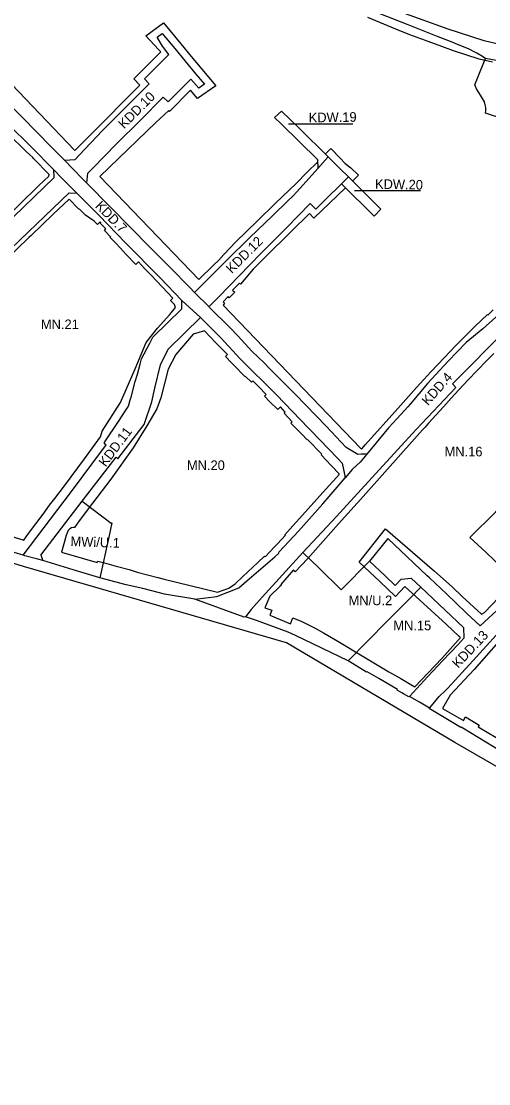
# Model space of a CAD drawing. Extents: x 7418991 to 7423142, y 5547704 to 5549547.
# Drawn here: x 7419792 to 7420035, y 5547967 to 5548519 of the extents above; entities that cross this region are included whole.
import ezdxf

# ---------------------------------------------------------------- set-up
doc = ezdxf.new("R2010")
doc.units = 0
for name, color, linetype in [('LIN_Linia Zabudowy Nieprzekraczalna', 7, 'Continuous'), ('LIN_linie_rozgraniczajace', 7, 'Continuous'), ('TXT_Oznaczenia_przeznaczen', 7, 'Continuous')]:
    doc.layers.add(name, color=color, linetype=linetype)

msp = doc.modelspace()

# ---------------------------------------------------------------- linework, layer by layer
at = {"layer": 'LIN_Linia Zabudowy Nieprzekraczalna'}
for p, q in [((7419717.86, 5548558.33), (7419819.96, 5548451.81)), ((7419832.95, 5548438.26), (7419884.28, 5548384.7)), ((7419821.98, 5548421.3), (7419816.95, 5548426.47))]:
    msp.add_line(p, q, dxfattribs=at)
for points in [[(7419856.71, 5548511.25), (7419866, 5548518.06), (7419874.96, 5548507.22)], [(7420036.89, 5548497.59), (7420029.91, 5548499.2), (7420016.68, 5548503.49), (7420010.54, 5548505.74), (7420001.59, 5548509.01), (7420000.65, 5548509.37), (7419999.62, 5548509.77), (7419994.01, 5548511.91), (7419986.71, 5548514.81), (7419972.13, 5548520.75)], [(7419864.51, 5548502.97), (7419863.34, 5548504.23), (7419856.71, 5548511.25)], [(7419874.96, 5548507.22), (7419880.38, 5548500.66), (7419885.89, 5548494.04)], [(7419853.63, 5548485.71), (7419850.46, 5548488.93), (7419864.51, 5548502.97)], [(7419885.89, 5548494.04), (7419893.15, 5548485.32), (7419883.63, 5548478.82), (7419880.01, 5548483)], [(7419819.96, 5548451.81), (7419824.06, 5548455.92), (7419835.48, 5548467.29), (7419845.95, 5548477.88), (7419853.63, 5548485.71)], [(7419880.01, 5548483), (7419869.06, 5548472.02), (7419868.65, 5548472.46)], [(7419868.65, 5548472.46), (7419862.06, 5548466.29), (7419832.95, 5548438.26)], [(7419781.33, 5548414.06), (7419801.15, 5548433.63), (7419806.37, 5548438.5), (7419806.42, 5548438.57), (7419806.59, 5548439.19), (7419806.59, 5548439.29), (7419798.4, 5548447.67), (7419798.01, 5548448.09), (7419794.66, 5548451.16), (7419785.41, 5548460.15)], [(7419950.06, 5548449.94), (7419952.85, 5548452.74), (7419957.74, 5548447.74), (7419960.34, 5548445.06), (7419963.22, 5548442.68), (7419967.33, 5548438.94), (7419964.17, 5548435.9)], [(7419927.77, 5548427.86), (7419934.85, 5548434.69), (7419940.39, 5548440.24), (7419946.07, 5548445.94)], [(7419960.56, 5548432.43), (7419944.13, 5548416.63), (7419941.75, 5548418.99), (7419932.21, 5548409.42), (7419918.92, 5548396.51), (7419912.58, 5548390.1), (7419906.02, 5548382.26), (7419905.49, 5548382.8), (7419901.88, 5548379.27), (7419903.02, 5548378.13), (7419900.1, 5548375.3), (7419899.58, 5548375.86), (7419896.89, 5548373.22), (7419897.74, 5548372.37), (7419896.98, 5548371.46), (7419968.26, 5548297.09), (7419968.51, 5548296.89), (7419968.91, 5548296.71), (7419968.99, 5548296.78), (7419970.97, 5548299.07), (7419987.7, 5548317.75), (7419989.04, 5548319.29), (7419997.5, 5548328.57), (7420005.13, 5548337), (7420011.92, 5548344.19), (7420017.73, 5548350.26), (7420022.47, 5548355.16), (7420027.89, 5548360.43), (7420034.37, 5548366.6), (7420034.6, 5548366.36), (7420037.35, 5548369.05)], [(7419816.95, 5548426.47), (7419808.61, 5548418.6), (7419797.18, 5548407.61), (7419796, 5548406.59), (7419783.69, 5548394.56), (7419776.16, 5548386.69), (7419769.62, 5548379.68), (7419753.04, 5548361.82), (7419741.07, 5548348.15), (7419710.14, 5548308.14)], [(7419884.28, 5548384.7), (7419892.01, 5548392.15), (7419894.73, 5548394.79), (7419894.67, 5548394.85), (7419897.35, 5548397.78), (7419903.59, 5548404.31), (7419914.74, 5548415.22), (7419924, 5548424.21), (7419927.77, 5548427.86)], [(7419825.49, 5548418.18), (7419822.22, 5548421.53), (7419821.98, 5548421.3)], [(7419831.61, 5548413.28), (7419829.86, 5548415.05), (7419825.49, 5548418.18)], [(7419838.26, 5548406.49), (7419838.55, 5548406.78), (7419835.26, 5548410.28), (7419835.93, 5548411.01), (7419833.08, 5548413.96), (7419833.37, 5548414.29), (7419833.04, 5548414.62), (7419831.61, 5548413.28)], [(7419851.5, 5548392.62), (7419846.6, 5548397.74), (7419843.51, 5548401.11), (7419841.11, 5548403.63), (7419838.26, 5548406.49)], [(7419869.61, 5548373.9), (7419870.87, 5548375.11), (7419862.42, 5548383.88), (7419862.16, 5548384.19), (7419859.91, 5548386.58), (7419857.53, 5548389.07), (7419856.17, 5548390.51), (7419852.89, 5548393.95), (7419851.5, 5548392.62)], [(7419872.18, 5548370.2), (7419871.63, 5548371.71), (7419869.61, 5548373.9)], [(7419793.36, 5548249.33), (7419795.77, 5548252.78), (7419803.35, 5548262.84), (7419806.75, 5548267.48), (7419809.48, 5548270.98), (7419814.44, 5548277.62), (7419824.91, 5548291.64), (7419833.15, 5548303.02), (7419834.02, 5548306.04), (7419843.53, 5548320.88), (7419851.31, 5548338.35), (7419857.02, 5548351.96), (7419862.92, 5548359.42), (7419869.17, 5548366.65), (7419872.18, 5548370.2)], [(7419881.32, 5548356.39), (7419872.45, 5548345.73), (7419868.34, 5548338.17), (7419864.5, 5548323.35), (7419862.57, 5548317.52), (7419857.38, 5548308.79), (7419850.18, 5548297.29), (7419838.64, 5548281.01), (7419829.13, 5548268.5), (7419822.19, 5548259.32), (7419819.63, 5548255.97), (7419819.17, 5548255.99), (7419818.13, 5548255.74), (7419817.23, 5548255.23), (7419816.38, 5548254.35), (7419815.83, 5548253.18), (7419815.45, 5548251.72), (7419812.99, 5548243.17)], [(7419898.13, 5548344.68), (7419899.18, 5548345.71), (7419893.22, 5548351.88), (7419887.23, 5548358.09), (7419881.32, 5548356.39)], [(7420037.56, 5548346.25), (7420034.04, 5548342.63), (7420028.9, 5548337.41), (7420024.36, 5548332.64), (7420019.35, 5548327.46), (7420015.38, 5548323.04), (7420011.45, 5548318.67), (7420003.62, 5548310.07), (7420001.92, 5548308.08), (7420000.59, 5548306.72), (7419983.76, 5548287.82), (7419966.88, 5548268.93), (7419966.59, 5548268.61), (7419956.98, 5548257.85), (7419940.9, 5548239.89), (7419937.52, 5548236.23), (7419934.39, 5548232.95), (7419933.38, 5548233.85), (7419926.89, 5548226.36), (7419927.23, 5548226.06), (7419926.49, 5548225.35), (7419921.2, 5548220.29), (7419918.67, 5548214.26), (7419922.2, 5548213.02), (7419921.13, 5548210.47), (7419931.88, 5548205.92), (7419933.15, 5548209.01), (7419937.77, 5548207.07), (7419944.69, 5548203.64), (7419949.06, 5548201.24), (7419957.46, 5548196.33), (7419968.37, 5548189.8), (7419975.29, 5548185.57), (7419983.04, 5548180.97), (7419989.2, 5548177.44), (7419994.53, 5548174.32), (7419996.6, 5548173.1), (7420010.57, 5548187.86), (7420019.11, 5548197.39), (7420020.09, 5548198.53), (7420020.04, 5548198.89), (7420019.63, 5548199.37), (7420012.79, 5548205.73), (7419991.3, 5548225.28), (7419986.55, 5548220.09), (7419978.32, 5548227.86), (7419967.58, 5548238), (7419981.37, 5548255.15), (7420006.78, 5548233.26), (7420015.93, 5548225.04), (7420021.1, 5548220.1), (7420031.14, 5548210.94), (7420032.76, 5548211.73), (7420051.25, 5548231.24)], [(7419908.23, 5548334.34), (7419902.47, 5548340.23), (7419901.22, 5548341.53), (7419898.13, 5548344.68)], [(7419918.39, 5548324.14), (7419919.32, 5548325.06), (7419915.43, 5548329.03), (7419914.39, 5548330.11), (7419912.45, 5548332.17), (7419911.64, 5548331.37), (7419908.46, 5548334.57), (7419908.23, 5548334.34)], [(7419925.31, 5548317.17), (7419921.12, 5548321.39), (7419918.39, 5548324.14)], [(7419932.21, 5548310.17), (7419932.89, 5548310.84), (7419928.62, 5548315.28), (7419929.25, 5548315.92), (7419926.7, 5548318.53), (7419926.09, 5548317.93), (7419925.31, 5548317.17)], [(7419940.57, 5548301.4), (7419937.78, 5548304.36), (7419932.21, 5548310.17)], [(7419947.82, 5548293.7), (7419948.18, 5548294.05), (7419940.78, 5548301.6), (7419940.57, 5548301.4)], [(7419953.08, 5548288.18), (7419950.5, 5548290.94), (7419948.01, 5548293.49), (7419947.82, 5548293.7)], [(7419954.23, 5548280.24), (7419957.18, 5548283.43), (7419957.3, 5548283.76), (7419957.27, 5548283.84), (7419956.92, 5548284.22), (7419953.83, 5548287.45), (7419953.08, 5548288.18)], [(7419929.05, 5548252.18), (7419933.2, 5548256.79), (7419936.62, 5548260.59), (7419945.7, 5548270.69), (7419953.79, 5548279.72), (7419954.23, 5548280.24)], [(7419721.51, 5548271.48), (7419724.57, 5548270.33), (7419733.19, 5548267.59), (7419747.21, 5548263.26), (7419762.91, 5548258.58), (7419769.84, 5548256.52), (7419780.42, 5548253.35), (7419793.36, 5548249.33)], [(7419918.37, 5548241.07), (7419918.8, 5548240.66), (7419923.72, 5548245.92), (7419925.18, 5548247.48), (7419929.34, 5548251.91), (7419929.05, 5548252.18)], [(7419812.99, 5548243.17), (7419831.57, 5548237.75), (7419831.77, 5548238.47), (7419835.32, 5548237.55), (7419841.41, 5548235.91), (7419848.1, 5548234.06), (7419852.27, 5548232.73), (7419863.05, 5548230), (7419866.32, 5548229.05), (7419894, 5548222.39)], [(7419894, 5548222.39), (7419899.88, 5548224.42), (7419903.28, 5548226.66), (7419907.12, 5548230.44), (7419914.92, 5548237.75), (7419918.37, 5548241.07)], [(7420046.24, 5548203.58), (7420027.46, 5548182.2), (7420014.87, 5548168.91), (7420010.87, 5548161.92), (7420021.77, 5548155.69), (7420022.83, 5548157.56), (7420030.02, 5548153.25), (7420029.5, 5548152.36), (7420038.8, 5548146.89)]]:
    msp.add_lwpolyline(points, dxfattribs=at)
at = {"layer": 'LIN_linie_rozgraniczajace'}
for p, q in [((7420042.19, 5548506.4), (7420032.55, 5548508.76)), ((7419826.12, 5548434.85), (7419826.66, 5548439.89)), ((7419882.1, 5548378.06), (7419898.9, 5548394.76)), ((7419894.69, 5548375.81), (7419889.72, 5548370.73)), ((7419941.38, 5548307.6), (7419924.62, 5548324.86)), ((7419982.47, 5548250.14), (7419973.01, 5548238.37)), ((7419802.26, 5548241.61), (7419803.19, 5548238.7))]:
    msp.add_line(p, q, dxfattribs=at)
for points in [[(7420032.55, 5548508.76), (7420013.86, 5548514.78), (7419989.73, 5548523.36), (7419965.32, 5548534.48), (7419945.27, 5548544.1)], [(7420325.12, 5547967), (7420017.42, 5548144.29), (7419955.38, 5548181), (7419929.91, 5548196.08), (7419793.21, 5548235.75), (7419596.81, 5548296.15), (7419558.42, 5548312.8), (7419546.12, 5548320.07), (7419546.12, 5548320.06), (7419504.75, 5548344.51), (7419463.08, 5548377.86), (7419457.25, 5548382.53), (7419446.13, 5548391.44), (7419408.3, 5548414.15), (7419403.6, 5548416.97), (7419403.3, 5548427.68), (7419403.28, 5548428.22), (7419403.44, 5548430.77), (7419403.61, 5548432.44), (7419404.03, 5548435.15), (7419413.56, 5548470.15), (7419425.07, 5548507.35), (7419431.26, 5548527.19)], [(7420028.02, 5548502.66), (7420024.52, 5548504.56), (7420017.85, 5548507.22), (7420016.8, 5548507.66), (7420007.79, 5548511.19), (7419993.01, 5548516.98), (7419973.97, 5548524.43)], [(7419730.82, 5548520.64), (7419749.71, 5548501.07), (7419751.69, 5548499.35), (7419754.06, 5548496.96), (7419759.39, 5548491.54), (7419762.83, 5548488.04), (7419767.29, 5548483.57), (7419775.92, 5548474.95), (7419785.15, 5548465.67), (7419797.38, 5548453.56), (7419809.02, 5548441.68), (7419813.1, 5548437.36), (7419820.94, 5548429.57), (7419832.45, 5548417.92), (7419846.22, 5548403.72), (7419864.18, 5548385.61), (7419875.46, 5548373.86), (7419885.22, 5548364.96), (7419895.76, 5548354.52), (7419905.88, 5548343.51), (7419924.62, 5548324.86)], [(7419868.8, 5548501.6), (7419865.39, 5548505.89), (7419862.59, 5548510.6), (7419865.32, 5548512.6), (7419871.87, 5548504.67)], [(7419868.8, 5548501.6), (7419856.1, 5548488.91), (7419858.55, 5548486.43), (7419846.59, 5548474.4), (7419834.23, 5548462.17), (7419822.13, 5548449.38)], [(7419871.87, 5548504.67), (7419877.3, 5548498.11), (7419882.82, 5548491.48)], [(7420102.05, 5548487.44), (7420098.3, 5548487.29), (7420094.85, 5548487.14), (7420080.12, 5548490.58), (7420072.4, 5548492), (7420049.93, 5548496.37), (7420033.21, 5548499.61), (7420032.5, 5548499.98), (7420031.64, 5548500.52), (7420028.77, 5548502.25), (7420028.02, 5548502.66)], [(7420059.04, 5548468.48), (7420061.98, 5548465.29), (7420064.91, 5548462.09), (7420064.8, 5548461.72), (7420064.7, 5548461.35), (7420050.83, 5548465.66), (7420036.97, 5548469.97), (7420033.31, 5548471.11), (7420033.41, 5548472.58), (7420033.51, 5548474.05), (7420033.15, 5548475.53), (7420032.78, 5548477), (7420030.7, 5548480.41), (7420028.62, 5548483.81), (7420027.7, 5548485.84), (7420030.46, 5548492.73), (7420033.21, 5548499.61)], [(7419829.47, 5548442.8), (7419841.32, 5548455.06), (7419853.75, 5548467.4), (7419865.78, 5548479.41), (7419868.32, 5548476.95), (7419880.21, 5548488.87)], [(7419882.82, 5548491.48), (7419887.26, 5548486.14), (7419884.32, 5548484.13), (7419880.21, 5548488.87)], [(7419889.76, 5548370.5), (7419882.1, 5548378.06), (7419879.58, 5548380.54), (7419869.45, 5548391), (7419859.11, 5548401.41), (7419838.3, 5548422.48), (7419826.12, 5548434.85), (7419823.92, 5548437.08), (7419818.94, 5548442.13), (7419814.47, 5548446.68), (7419807.54, 5548453.72), (7419792.57, 5548469.04), (7419782.56, 5548478.75)], [(7419951.56, 5548448.44), (7419936.49, 5548463.43), (7419927.3, 5548472.22), (7419923.59, 5548468.9), (7419927.26, 5548465.45), (7419946.02, 5548447.15), (7419946.22, 5548442.43)], [(7419814.47, 5548446.68), (7419820, 5548447.13), (7419822.13, 5548449.38)], [(7419935.49, 5548430.37), (7419946.22, 5548442.43), (7419951.56, 5548448.44)], [(7419951.56, 5548448.44), (7419957.62, 5548442.41), (7419962.04, 5548438.02)], [(7419711.52, 5548336.84), (7419718.53, 5548346.58), (7419723.44, 5548347.14), (7419745.99, 5548375.71), (7419749.05, 5548379.46), (7419767.7, 5548397.59), (7419771.93, 5548401.71), (7419783.05, 5548412.46), (7419809.15, 5548437.71), (7419809.02, 5548441.68)], [(7419826.66, 5548439.89), (7419827.38, 5548440.62), (7419829.47, 5548442.8)], [(7419894.69, 5548375.81), (7419910.69, 5548392.16), (7419916.76, 5548398.39), (7419930.03, 5548411.74), (7419942.22, 5548424.15), (7419945.07, 5548421.33), (7419950.07, 5548426.25), (7419958.47, 5548434.51), (7419962.04, 5548438.02)], [(7419958.47, 5548434.51), (7419975.42, 5548417.62), (7419978.96, 5548421.21), (7419962.04, 5548438.02)], [(7419709.69, 5548311.91), (7419721.08, 5548326.49), (7419732.33, 5548341.35), (7419742.43, 5548353.99), (7419743.97, 5548355.73), (7419756.88, 5548371.75), (7419769.48, 5548384.13), (7419775.41, 5548389.8), (7419782.19, 5548396.29), (7419795.85, 5548409.55), (7419816.87, 5548429.82), (7419820.94, 5548429.57)], [(7419898.9, 5548394.76), (7419910.6, 5548406.39), (7419922.81, 5548417.9), (7419930.45, 5548425.4), (7419933.23, 5548428.02), (7419935.49, 5548430.37)], [(7420101.88, 5548428.64), (7420099.58, 5548425.39), (7420094.14, 5548414.63), (7420089.44, 5548410.27), (7420086.07, 5548407.13), (7420078.82, 5548400.46), (7420059, 5548384.29), (7420056.7, 5548382.17), (7420053.1, 5548378.85), (7420043.71, 5548369.75), (7420031.87, 5548359.17), (7420023.15, 5548351.99), (7420013.93, 5548342.29), (7420003.1, 5548330.8)], [(7420158.48, 5548387.04), (7420126.91, 5548388.97), (7420117.31, 5548399.77), (7420110.75, 5548407.15), (7420092.89, 5548399.22), (7420084.49, 5548392.8), (7420058.27, 5548372.81), (7420044.54, 5548359.06), (7420016.1, 5548330.54), (7420017.89, 5548328.64), (7419997.32, 5548306.91), (7419972.24, 5548279.73), (7419955.89, 5548261.61), (7419938.28, 5548242.93), (7419917.3, 5548219.73), (7419911.59, 5548213.29), (7419908.65, 5548209.49)], [(7419853.81, 5548340.81), (7419854.44, 5548343.48), (7419858.83, 5548351.72), (7419860.47, 5548354.77), (7419875.51, 5548369.43), (7419875.46, 5548373.86)], [(7419934.61, 5548324.98), (7419928.12, 5548331.49), (7419922.88, 5548336.69), (7419920.84, 5548338.65), (7419918.39, 5548341.22), (7419911.92, 5548347.55), (7419904.73, 5548355.27), (7419900.58, 5548359.6), (7419889.83, 5548370.14), (7419889.76, 5548370.5), (7419889.72, 5548370.73)], [(7419841.3, 5548292.47), (7419842.16, 5548291.6), (7419855.84, 5548309.42), (7419859.93, 5548321.24), (7419861.54, 5548328.36), (7419864.37, 5548340.42), (7419868.31, 5548348.48), (7419885.22, 5548364.96)], [(7419836.25, 5548298.77), (7419835.17, 5548299.83), (7419842.96, 5548311.42), (7419845.77, 5548315.76), (7419847.72, 5548318.94), (7419848.68, 5548322.26), (7419849.08, 5548323.59), (7419851.25, 5548331.78), (7419852.46, 5548335.56), (7419853.81, 5548340.81)], [(7420003.1, 5548330.8), (7419994.05, 5548319.95), (7419992.96, 5548318.64), (7419987.35, 5548312.6), (7419982.85, 5548307.74), (7419971.68, 5548294.03), (7419968.23, 5548289.78), (7419964.07, 5548286.14), (7419960.31, 5548281.77)], [(7419971.68, 5548294.03), (7419968.81, 5548293.98), (7419966.96, 5548293.78), (7419960.94, 5548297.5), (7419950.49, 5548308.57), (7419934.61, 5548324.98)], [(7419941.38, 5548307.6), (7419942.33, 5548306.54), (7419956.52, 5548291.7), (7419958.76, 5548289.37), (7419959.94, 5548283.62), (7419960.31, 5548281.77)], [(7419793.02, 5548241.57), (7419807.22, 5548260.33), (7419818.11, 5548274.65), (7419828.66, 5548288.83), (7419835.83, 5548298.26), (7419836.25, 5548298.77)], [(7419802.26, 5548241.61), (7419823.77, 5548269.62), (7419841.3, 5548292.47)], [(7419882.17, 5548218.78), (7419893.66, 5548220.03), (7419905.08, 5548224.59), (7419909.32, 5548228.24), (7419923.84, 5548240.76), (7419925.9, 5548242.53), (7419926.02, 5548243.34), (7419936.1, 5548254), (7419948.71, 5548268.27), (7419951.99, 5548272.09), (7419960.31, 5548281.77)], [(7420055.95, 5548277.38), (7420081.86, 5548252.52), (7420067.24, 5548238.84), (7420052.3, 5548224.88), (7420044.01, 5548232.93), (7420038.12, 5548238.54), (7420033.38, 5548243.06), (7420025.21, 5548250.74), (7420038.69, 5548264.06), (7420039.67, 5548265.29)], [(7419823.77, 5548269.62), (7419838.85, 5548258.11), (7419839.16, 5548258.36), (7419837.51, 5548250.83), (7419832.89, 5548229.72)], [(7419793.02, 5548241.57), (7419774.07, 5548247.15), (7419751.56, 5548254.2), (7419721.32, 5548264)], [(7420013.74, 5548172.54), (7420028.67, 5548188.72), (7420044.03, 5548205.64), (7420050.93, 5548212.94), (7420057.48, 5548220.19), (7420053.74, 5548223.57), (7420052.3, 5548224.88), (7420030.5, 5548204.84), (7420023.66, 5548211.31), (7420017.89, 5548216.78), (7420012.97, 5548221.44), (7420004.18, 5548229.76), (7420003, 5548230.83), (7419992.53, 5548240.75), (7419982.47, 5548250.14)], [(7419855.14, 5548224.19), (7419846.5, 5548226.11), (7419832.89, 5548229.72), (7419819.1, 5548233.88), (7419803.19, 5548238.7), (7419800.62, 5548239.48), (7419793.9, 5548241.2), (7419793.02, 5548241.57)], [(7419938.28, 5548242.93), (7419946.66, 5548234.98), (7419958.21, 5548223.5), (7419973.01, 5548238.37)], [(7419973.01, 5548238.37), (7419981.07, 5548230.77), (7419986.34, 5548225.79), (7419989.4, 5548229.13), (7419994.69, 5548229.63), (7419999.7, 5548224.91), (7420012.39, 5548212.94), (7420021.84, 5548204.03), (7420022.01, 5548198.37), (7420018.88, 5548195.06), (7420011.17, 5548186.84), (7420003.35, 5548178.52), (7419993.71, 5548168.13)], [(7419882.17, 5548218.78), (7419866.45, 5548221.36), (7419863.87, 5548222), (7419855.14, 5548224.19)], [(7419961.9, 5548186.64), (7419971.84, 5548196.76), (7419982.37, 5548207.39), (7419993.71, 5548218.84), (7419999.7, 5548224.91)], [(7419993.5, 5548167.9), (7419990.68, 5548169.56), (7419989.8, 5548170.08), (7419987.42, 5548171.44), (7419987.47, 5548171.79), (7419977.82, 5548177.42), (7419971.8, 5548180.91), (7419971.51, 5548180.78), (7419961.9, 5548186.64), (7419934.63, 5548199.76), (7419930.76, 5548201.49), (7419914.21, 5548207.55), (7419908.65, 5548209.49), (7419907.87, 5548209.36), (7419882.17, 5548218.78)], [(7420004.21, 5548162.16), (7420004.35, 5548162.32), (7420009.2, 5548168.23), (7420012.46, 5548171.22), (7420013.74, 5548172.54)], [(7420020.65, 5548152.15), (7420020.55, 5548152.07), (7420004.06, 5548161.97), (7420004.21, 5548162.16), (7419998.95, 5548165.15), (7419993.71, 5548168.13), (7419993.5, 5548167.9)], [(7420100.28, 5548104.74), (7420094.4, 5548108.51), (7420089.7, 5548111.23), (7420088.3, 5548112.05), (7420058.44, 5548129.6), (7420057.5, 5548130.02), (7420049.19, 5548135.03), (7420047.23, 5548136.04), (7420041.36, 5548139.54), (7420021.57, 5548151.65), (7420020.65, 5548152.15)]]:
    msp.add_lwpolyline(points, dxfattribs=at)
at = {"layer": 'TXT_Oznaczenia_przeznaczen'}
for p, q in [((7419930.96, 5548465.54), (7419964.26, 5548465.54)), ((7419965.28, 5548430.92), (7419999.44, 5548430.92))]:
    msp.add_line(p, q, dxfattribs=at)

# ---------------------------------------------------------------- texts
for s, rotation, p in [('KDD.10', 44.9033, (7419845.43, 5548462.71)), ('KDW.19', 0.9586, (7419941.45, 5548466.3)), ('KDW.20', 358.8562, (7419975.83, 5548431.91)), ('KDD.7', 314.3579, (7419830.12, 5548422.59)), ('KDD.12', 44.9033, (7419901.45, 5548387.55)), ('KDD.4', 48.4383, (7420003.39, 5548318.94)), ('KDD.11', 52.9475, (7419835.85, 5548287.08)), ('MWi/U.1', 357.9964, (7419817.58, 5548246.29)), ('KDD.13', 46.655, (7420019.05, 5548182.54))]:
    msp.add_text(s, height=5, rotation=rotation, dxfattribs=at).set_placement(p)
for s, p in [('MN.21', (7419802.26, 5548358.95)), ('MN.16', (7420012.03, 5548292.85)), ('MN.20', (7419878.14, 5548285.76)), ('MN/U.2', (7419962.14, 5548215.57)), ('MN.15', (7419985.38, 5548202.55))]:
    msp.add_text(s, height=5, dxfattribs=at).set_placement(p)

doc.saveas('drawing.dxf')
